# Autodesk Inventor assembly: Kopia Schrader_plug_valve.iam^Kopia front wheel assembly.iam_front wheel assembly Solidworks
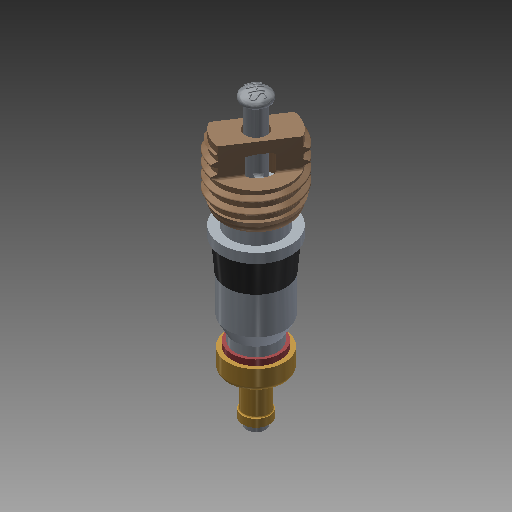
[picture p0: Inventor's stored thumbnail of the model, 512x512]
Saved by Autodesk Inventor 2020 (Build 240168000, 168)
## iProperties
Created: 2017-09
Part Number: Kopia Schrader_plug_valve.iam^Kopia front wheel assembly.iam_front wheel assembly Solidworks
Material: Ogólny
Document SubType Name: Assembly
Designer: Tomasz
Sending System: SolidWorks 2017
Last Author: Tomasz
Last Saved: 2017-09-11
Author: Tomasz
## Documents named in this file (2)
- C:\Users\bruno\Documents\1-Cours-2020-21\1STI2D-2020-21\IT\6. Antivol\Inventor-Antivol\INVENTOR 2018_Steel Hardtail B+\Kopia Schrader_plug_valve.iam^Kopia front wheel assembly.iam_front wheel assembly Solidworks.iam
- C:\Users\bruno\Documents\1-Cours-2020-21\1STI2D-2020-21\IT\6. Antivol\Inventor-Antivol\INVENTOR 2018_Steel Hardtail B+\Kopia Schrader_bicycle_valve-00.iam^Kopia Schrader_plug_valve.iam_Kopia front wheel assembly.iam_front wheel assembly.iam
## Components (1 placed, 1 different names)
1. Kopia Schrader_bicycle_valve-00.iam^Kopia Schrader_plug_valve.iam_Kopia front wheel assembly.iam_front wheel assembly Solidworks:1 [sub-assembly]
